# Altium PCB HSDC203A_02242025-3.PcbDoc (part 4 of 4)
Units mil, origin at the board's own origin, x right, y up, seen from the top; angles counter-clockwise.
Board outline 5612.98 x 3012.39 mil, 6 copper layers (Top Layer, GND1, Signal1, Power, GND2, Bottom Layer), stack 60.4 mil thick; 301 components, 211 nets, 1107 pads, 249 vias.
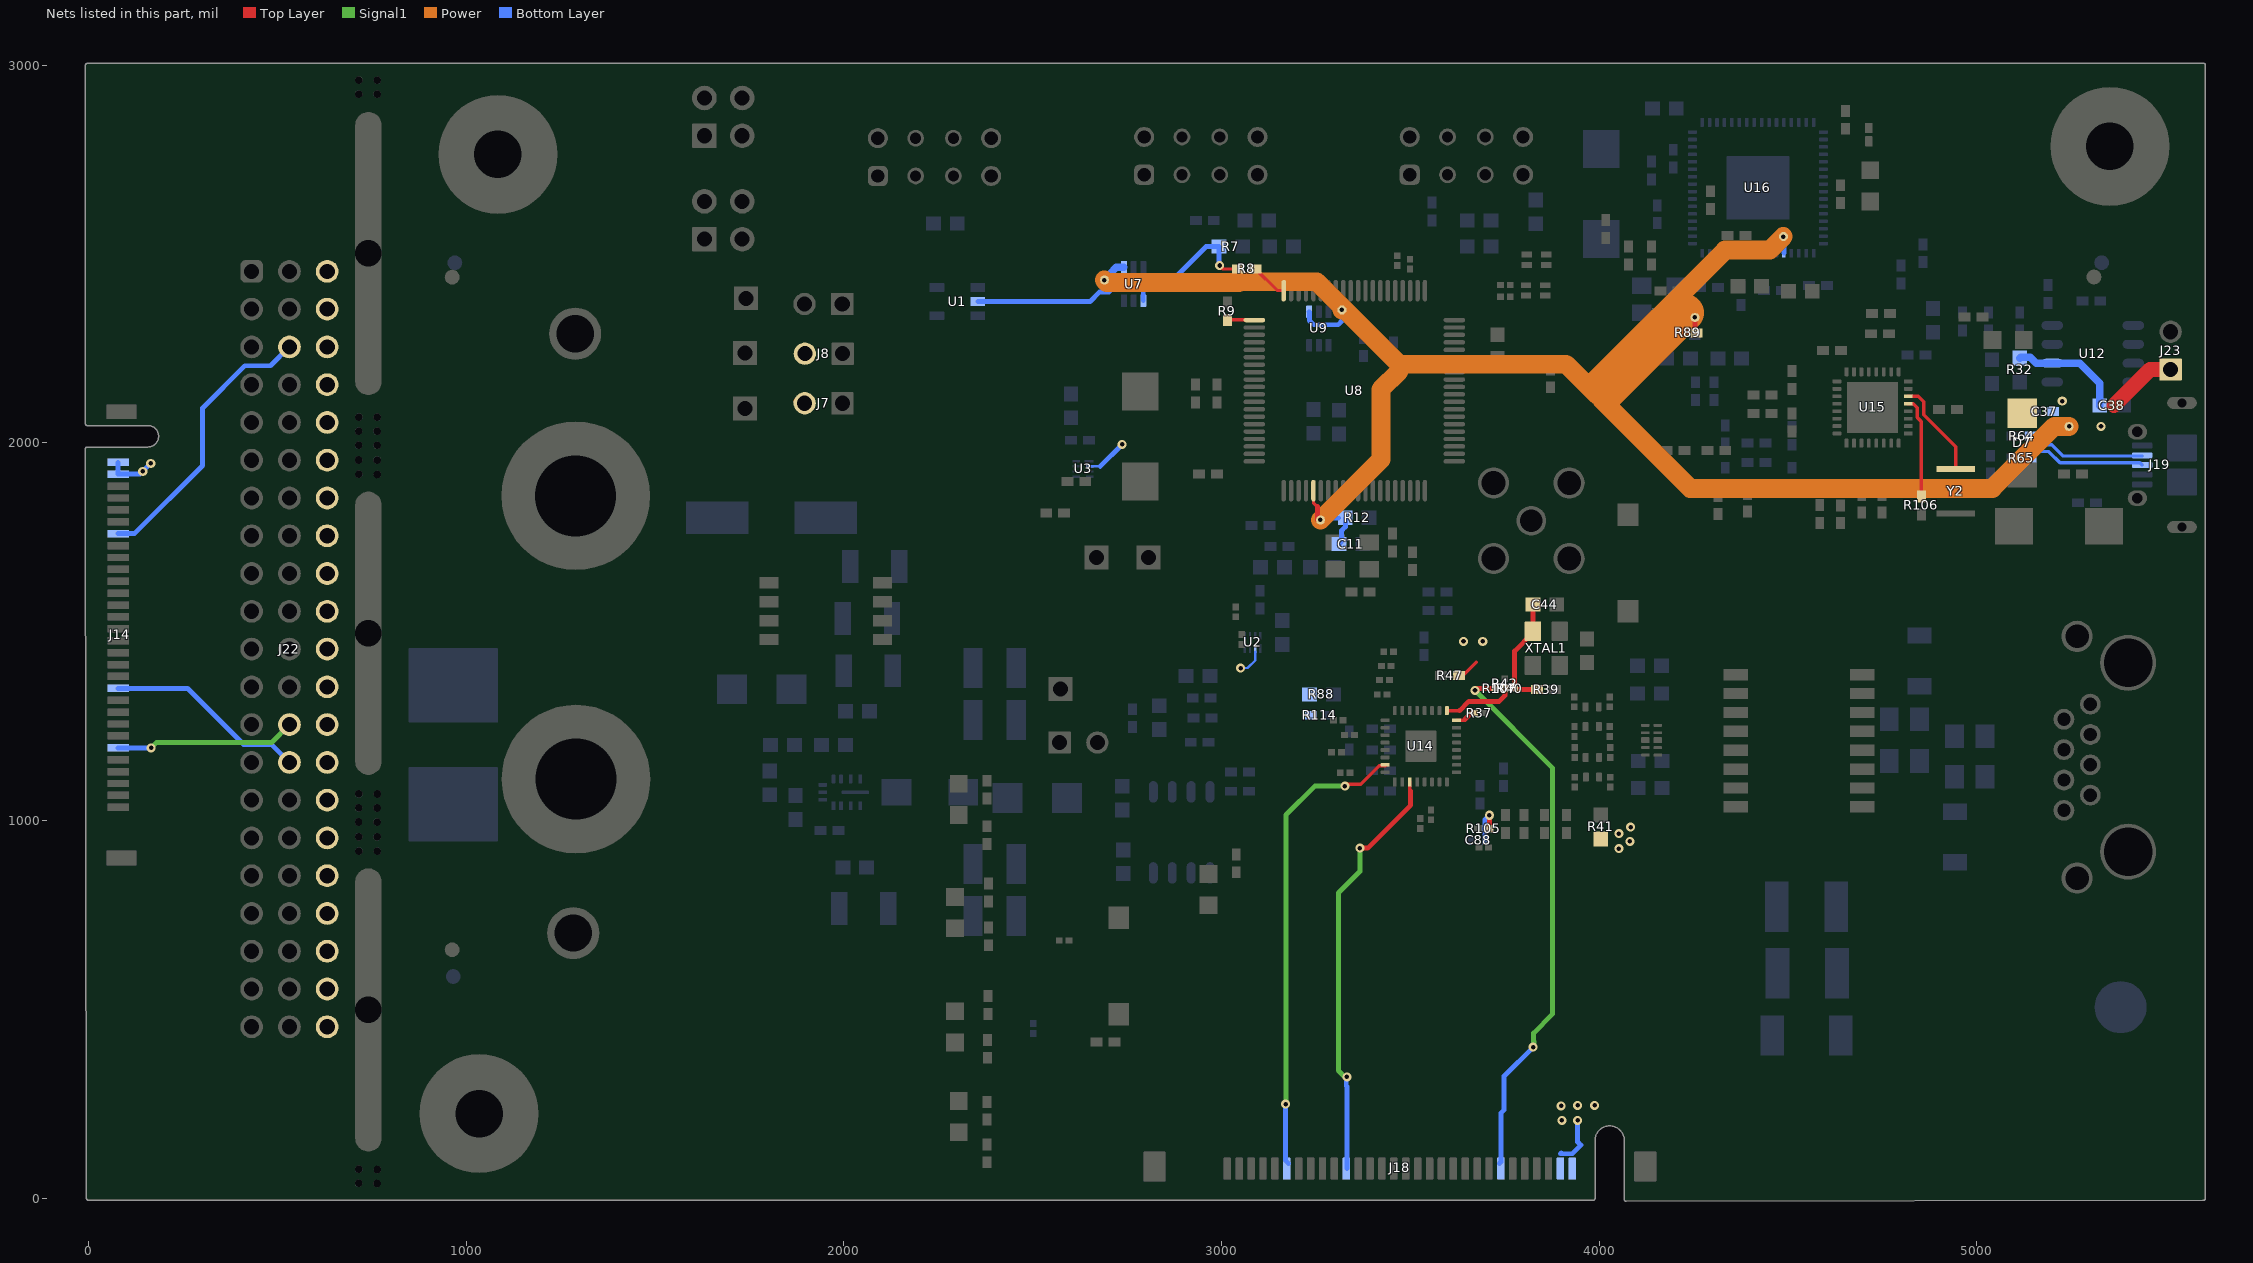
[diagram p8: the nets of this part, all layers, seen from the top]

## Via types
v1: diameter 24, hole 12, Top Layer to Bottom Layer, tented both sides, 227 vias
v2: diameter 19.68, hole 7.87, Top Layer to Bottom Layer, 17 vias
v3: diameter 19.68, hole 7.87, Top Layer to Bottom Layer, tented both sides, 5 vias

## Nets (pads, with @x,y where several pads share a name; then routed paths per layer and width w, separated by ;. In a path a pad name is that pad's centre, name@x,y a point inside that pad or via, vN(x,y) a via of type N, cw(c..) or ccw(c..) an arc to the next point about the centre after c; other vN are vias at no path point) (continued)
TX_D3: J18.40 U14.27 | length 1130.5
  Top Layer w9: 3498.34,1077.61 U14.27@3498.3,1102.52
  Top Layer w13: v1(3366.56,927.23) 3386.94,927.23 3500.71,1041.01 3500.71,1078.06 3499.75,1079.02
  Signal1 w13: v1@3330.32,317.53 3309.59,338.25 3309.59,808.85 3366.56,865.82 v1(3366.56,927.23)
  Bottom Layer w13: v1(3331.83,321.47) 3330.32,319.96 3330.32,297.53 3331.9,295.94 J18.40@3331.9,78.74
TX_D3_EXT: J14.40 J22.41 | length 534.7
  Bottom Layer w13: J14.40@78.74,1350.39 262.3,1350.39 410.69,1202 484.65,1202 J22.41@532.28,1154.36
TX_EN: J18.50 U14.23 | length 1244.5
  Top Layer w9: v1(3326.62,1091.36) 3331.25,1096 3368.18,1096 3417.59,1145.41 3433.38,1145.41 U14.23@3433.38,1147.8
  Signal1 w13: v1@3170.87,249.44 3170.87,1015.42 3246.8,1091.36 v1(3326.62,1091.36)
  Bottom Layer w13: v1(3169.82,249.44) 3169.82,99.82 J18.50@3176.97,92.66
TX_EN_EXT: J14.50 J22.38 | length 479
  Signal1 w13: v1(165.87,1192.91) 179.75,1206.79 484.71,1206.79 J22.38@532.28,1254.36
  Bottom Layer w13: J14.50@78.74,1192.91 v1(165.87,1192.91)
TX_OPT: R7.1 R8.1 U1.2 U7.4 | length 841.4
  Top Layer w9: v1(2994.85,2469.85) 3004.08,2460.63 R8.1@3043.17,2460.63
  Bottom Layer w13: U1.2@2354.59,2374.33 2651.69,2374.33 2677.39,2400.03 2702.59,2400.03 2720.45,2417.88 2782.71,2417.88 2792.91,2407.68 ; U7.4@2792.91,2376.57 2792.91,2407.68 ; 2805.6,2407.67 2846.68,2407.67 2958.92,2519.91 R7.1@2993.17,2519.91 2993.17,2471.53 v1(2994.85,2469.85) ; 2805.59,2407.68 2792.91,2407.68
UART_RX: R9.2 U8.41 | length 72.1
  Top Layer w9: R9.2@3015.35,2324.8 3016.57,2326.02 U8.41@3086.92,2326.02
UART_TX: R8.2 U8.40 | length 97.8
  Top Layer w9: R8.2@3090.42,2460.63 3147.27,2403.77 U8.40@3164.67,2403.77
USB_N: J19.2 R64.1 | length 316.8
  Bottom Layer w9: R64.1@5142.86,2018.93 5166.48,1995.31 5197.66,1995.31 5227.34,1965.63 J19.2@5437.6,1965.63
USB_P: J19.3 R65.1 | length 318.1
  Bottom Layer w9: R65.1@5141.42,1959.88 5158.85,1977.31 5190.2,1977.31 5219.89,1947.63 5431.68,1947.63 J19.3@5437.6,1941.71
USB_VBUS: C11.2 C37.1 C38.1 D7.1 J23.1 R12.2 R32.2 R89.2 U7.1 U8.65 U9.1 U12.2 U16.53 | length 5335.8
  Top Layer w9: U8.65@3243.41,1874.25 U8.65@3243.41,1873.69 3243.41,1841.98 3253.83,1831.57
  Top Layer w13: v1@3253.83,1796.15 3253.83,1831.57 ; v1(4253.53,2332.67) 4253.53,2295.5 R89.2@4257.75,2291.28
  Top Layer w40: 5363.12,2099.48 5458.05,2194.41 J23.1@5512.8,2194.41
  Power w50: v1(2689.66,2431.26) 2695.94,2424.98 3046.42,2424.98 3048.21,2426.76 3252.08,2426.76 3318.5,2360.34 v1(3318.5,2352.36) 3326.48,2352.36 3470.4,2208.44 ; v1@3262.16,1796.36 3422.01,1956.22 3422.01,2142.05 3470.4,2190.43 3470.4,2208.44 ; 3994.68,2126.21 3959.96,2160.92 ; 4007.48,2139.01 4007.48,2113.41 4240.96,1879.92 5040.94,1879.92 5204.99,2043.96 v1(5244.21,2043.96) ; v1(4487.31,2546.45) 4451.5,2510.63 4333.16,2510.63 3983.45,2160.92 3959.96,2160.92 ; 3470.4,2208.44 3912.45,2208.44 3959.96,2160.92
  Power w100: 4024.7,2142.18 4227.55,2345.03
  Bottom Layer w13: U9.1@3232.11,2347.44 3233.07,2346.48 3233.07,2324.04 3244.12,2312.99 3308.66,2312.99 3318.5,2322.83 v1(3318.5,2352.36) v1@3318.5,2356.73 ; v1@3266.81,1801.02 R12.2@3310.34,1801.02 ; C11.2@3310.9,1732.28 3317.82,1739.2 3317.82,1767.87 3327.75,1777.79 R12.2@3327.75,1802 ; v1(4487.31,2546.45) 4489.06,2544.7 U16.53@4489.06,2502.28
  Bottom Layer w20: v1(2689.66,2431.26) 2721.4,2465.16 U7.1@2741.73,2465.16 ; R32.2@5113.3,2224.89 5115.8,2227.4 5140.56,2227.4 5156.74,2211.22 U12.2@5199.41,2211.22 5272.51,2211.22 5325.16,2158.58 C38.1@5325.16,2099.18
  other v1: 3261.94,1796.15 5328.46,2043.96 5225.87,2110.72
VDDA3P3: J7.2 R41.2 | length 14.8
  Power w25: J7.2@1879.75,2109.78 J7.2@1894.53,2109.78
  other v1: 4051.85,926.25 4081.38,945.27 4051.85,965.81 4082.86,982.99
VDDIO: C88.2 J8.2 J18.2 J18.4 R47.2 R88.1 R105.2 R114.1 U2.2 U3.2 | length 488.3
  Top Layer w9: R47.2@3628.26,1384.29 3633.57,1378.97 3674.28,1419.68
  Top Layer w13: R105.2@3709.26,978.33 v1(3709.26,1014.46)
  Bottom Layer w6: U3.2@2651.18,1938.22 2679.01,1938.22 ; v1(3050.48,1403.97) 3068.93,1403.97 3089.17,1424.21 U2.2@3089.17,1447.87
  Bottom Layer w12: 3899.61,120.47 3897.24,118.11 3928.74,118.11
  Bottom Layer w13: 2679.01,1938.22 v1(2736.89,1996.1) ; C88.2@3698.04,948.8 3698.04,1003.24 v1(3709.26,1014.46) ; 3928.74,118.11 3951.48,140.85 3942.9,149.44 v1(3942.9,206.69)
  other v1: 3901.38,206.69 3899.21,245.02 3942.58,246.06 3987.8,246.06 3640.71,1474.91 3691.61,1474.91
VDDIO_EXT: J14.2 J14.4 J22.3 J22.6 J22.9 J22.12 J22.15 J22.18 J22.21 J22.24 J22.27 J22.30 J22.33 J22.36 J22.39 J22.42 J22.45 J22.48 J22.51 J22.54 J22.57 J22.60 J22.63 | length 129.8
  Bottom Layer w13: J14.2@78.74,1948.82 J14.4@78.74,1917.32 136.26,1917.32 v1(143.88,1924.94) v1(165.09,1946.16)
XI: R40.1 R42.2 R107.1 U14.9 | length 188.2
  Top Layer w9: U14.9@3596.76,1291.5 3630.48,1291.5
  Top Layer w13: 3630.48,1291.5 3655.01,1316.02 3734.89,1316.02 3750.11,1331.24 R40.1@3750.11,1349.64
XI_C: C44.1 R39.1 R40.2 XTAL1.1 | length 303.1
  Top Layer w13: C44.1@3824.48,1571.94 3824.48,1501.65 XTAL1.1@3824.41,1501.57 3824.41,1497.36 3776.1,1449.05 R40.2@3776.1,1349.64 3778.69,1347.04 R39.1@3835.74,1347.04
XI_S: J18.14 R107.2 | length 1447
  Top Layer w13: v1@3672.35,1347.04 3674.95,1349.64 R107.2@3724.13,1349.64
  Signal1 w13: v1(3671.12,1345.24) 3876.14,1140.21 3876.14,487.51 3826.36,437.72 3826.36,415.87 3827.17,415.06 v1@3827.17,401.58
  Bottom Layer w13: J18.14@3735.63,92.66 3739.76,96.8 3739.76,225.87 3748.42,234.53 3748.42,323.92 v1(3824.86,400.35)
XI_S_EXT: J14.14 J22.8 | length 747.6
  Bottom Layer w13: J14.14@78.74,1759.84 121.76,1759.84 302.41,1940.5 302.41,2092.73 414.05,2204.36 482.28,2204.36 J22.8@532.28,2254.36
XO: R37.2 U14.8 | length 55.3
  Top Layer w9: U14.8@3622.35,1265.91 3645.31,1265.91
  Top Layer w13: 3644.49,1267.91 3661.62,1285.05 R37.2@3669.69,1285.05
XTAL1: U15.30 Y2.1 | length 259.7
  Top Layer w9: U15.30@4818.22,2123.46 4844.63,2123.46 4859.31,2108.77 4859.31,2074.43 4944.01,1989.74 Y2.1@4944.01,1931.33
XTAL2: R106.2 U15.29 | length 268.1
  Top Layer w9: U15.29@4818.22,2103.77 4831.84,2103.77 4842.4,2093.21 4842.4,2080.49 4842.44,2080.46 4842.44,2067.44 4853.04,2056.84 R106.2@4853.04,1858.1
pads on no net: FID1.1 FID2.1 FID3.1 FID4.1 FID5.1 FID6.1 H5.0 H6.0 H7.0 H8.0 J14.17 J14.33 J14.53 J14.57 J14.59 J18.17 J18.33 J18.53 J18.57 J18.59 J19.4 T2.4 T2.5 T2.12 T2.13 U1.1 U4.1 U4.4 U4.5 U4.8 U5.1 U5.4 U5.5 U5.8 U6.1 U6.4 U6.5 U6.8 U8.1 U8.2 U8.3 U8.5 U8.6 U8.7 U8.8 U8.9 U8.10 U8.12 U8.13 U8.15 U8.16 U8.17 U8.27 U8.29 U8.30 U8.31 U8.32 U8.33 U8.34 U8.35 U8.36 U8.37 U8.38 U8.39 U8.42 U8.43 U8.44 U8.45 U8.48 U8.53 U8.54 U8.55 U8.56 U8.57 U8.58 U8.59 U8.60 U8.72 U8.73 U8.74 U8.75 U10.8 U13.3@4122.24,1213.15 U13.8@4155.12,1213.15 U15. U15.5 U15.9 U15.13 U15.17 U15.21 U15.32 U16.3 U16.4 U16.5 U16.6 U16.7 U16.8 U16.10 U16.12 U16.13 U16.18 U16.19 U16.22 U16.23 U16.24 U16.25 U16.26 U16.27 U16.28 U16.29 U16.30 U16.31 U16.34 U16.35 U16.36 U16.41 U16.42 U16.45 U16.46 U16.47 U16.48 U16.60 U16.61 U16.62 U16.63

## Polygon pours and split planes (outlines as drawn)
GND_EXT on Bottom Layer "BOTTOM_LAYER_GND_EXT_P156" (solid, remove dead copper, pour order 156): 0,3000 0,8.46 680.71,8.46 680.71,3000
GND on Bottom Layer "NONET_L01_P-001" (solid, pour order 10): 4070.03,844.13 4503.76,844.13 4503.76,215.91 4070.83,215.91
VDDIO on Bottom Layer "BOTTOM_LAYER_VDDIO_P011" (solid, remove dead copper, pour order 11): 3974.5,50.86 3974.5,180.4 4005.32,211.52 4004.96,265.27 3885.59,265.27 3885.59,50.86
5V on Bottom Layer "BOTTOM_LAYER_5V_P013" (solid, remove dead copper, pour order 13): 2301.43,1511.73 2301.43,663.16 2706.76,663.16 2706.76,1419.27 2614.3,1511.73
5V-12V on Bottom Layer "BOTTOM_LAYER_5V-12V_P019" (solid, remove dead copper, pour order 19): 1791.94,1910.91 2090.15,1910.92 2090.15,712.6 1791.94,712.6
NetJ4_1 on Bottom Layer "BOTTOM_LAYER_NETJ4_1_P022" (solid, remove dead copper, pour order 22): 1559.21,1318.9 1559.21,514.54 970.28,514.54 cw(c970.28,654.91) 829.91,654.91 829.91,1318.9
no net on Bottom Layer "BOTTOM_LAYER_NONET_P023" (solid, remove dead copper, pour order 23): 907.08,1545.28 1300.79,1545.28 1300.79,1654.36 1507.48,1654.36 1507.48,2369.2 ccw(c1416.05,2369.2) 1416.05,2460.63 936.38,2460.63 ccw(c936.38,2362.44) 838.19,2362.44 838.19,1614.17 ccw(c907.08,1614.17)
MCU_VCC on Bottom Layer "BOTTOM_LAYER_MCU_VCC_P027" (solid, remove dead copper, pour order 27): 4727.89,2312.99 4731,2211.73 5049.51,2207.35 5049.51,2245.67 5234.71,2245.67 5234.71,2312.99
USB_VBUS on Bottom Layer "BOTTOM_LAYER_USB_VBUS_P035" (solid, remove dead copper, pour order 35): 5094.32,2242.08 5094.32,2189.55 5183.22,2189.55 5183.22,2028.27 5355.91,2028.27 5355.91,2242.08
GND on Bottom Layer "BOTTOM_LAYER_GND_P104" (solid, remove dead copper, pour order 104): 2994.73,155.12 2994.73,50.86 3957.48,50.86 3957.48,155.12
no net on Bottom Layer "BOTTOM_LAYER_NONET_P112" (solid, remove dead copper, pour order 112): 840.84,1538.62 840.84,1257.68 1300.79,1257.68 1300.79,1538.62
NetD3_1 on Bottom Layer "BOTTOM_LAYER_NETD3_1_P116" (solid, remove dead copper, pour order 116): 2532.57,1245.7 2532.28,999.63 2659.06,999.63 2659.06,1119.22 2615.75,1119.22 2615.75,1245.7
Sys_5V on Bottom Layer "BOTTOM_LAYER_SYS_5V_P120" (solid, remove dead copper, pour order 120): 2629.37,1267.91 2629.37,1054.36 2845.77,1054.36 2845.77,994.71 2885.82,994.71 2885.82,1267.91
VDDIO on Bottom Layer "BOTTOM_LAYER_VDDIO_P132" (solid, remove dead copper, pour order 132): 3028.01,1419.47 3028.01,1259.41 3253.83,1259.41 3253.83,1419.47
3V3_OPT on Bottom Layer "BOTTOM_LAYER_3V3_OPT_P134" (solid, remove dead copper, pour order 134): 2568.42,2102.74 2639.37,2102.74 2639.37,2147.31 2954.3,2147.31 2954.37,2269.05 2568.42,2269.05
MCU_VCC on Bottom Layer "BOTTOM_LAYER_MCU_VCC_P136" (solid, remove dead copper, pour order 136): 3930.1,2712.14 3930.1,2482.27 4127.06,2482.27 4133.15,2482.27 4133.15,2488.36 4133.15,2653.55 4165.43,2653.55 4216.47,2704.59 4216.47,2752.74 4217.6,2753.86 4148.51,2753.86 4149.89,2712.14
3V3_LDO on Bottom Layer "BOTTOM_LAYER_3V3_LDO_P146" (solid, remove dead copper, pour order 146): 1944.28,2435.35 1947.18,2432.45 1947.18,1975.43 2087.83,1975.43 2237.47,1825.8 2237.47,1700.28 2237.47,1553.51 2544.59,1553.51 2736.71,1553.51 2736.71,1511.91 2773.52,1489.65 2783,1494.62 2793.62,1579.48 2652.62,1660.97 2442.52,2025.08 2442.52,2295.73 2129.32,2295.73 2139.37,2305.79 2139.37,2435.35
3V3_LDO on Bottom Layer "BOTTOM_LAYER_3V3_LDO_P147" (solid, remove dead copper, pour order 147): 2662.8,1634.67 2662.8,1560.49 2750.26,1473.03 2842.47,1473.03 2842.47,931.17 2962.23,931.17 2962.23,1634.67
GND on Bottom Layer "BOTTOM_LAYER_GND_P148" (solid, remove dead copper, pour order 148): 800.76,3020.11 800.76,-7.38 4263.12,-7.38 4263.12,1793.62 5603.19,1793.62 5603.19,3020.11
EARTH_GND on Bottom Layer "Bottom Layer-EARTH_GND" (solid, remove dead copper, pour order 151): 5045.26,361.97 5598.04,361.97 5598.04,624.69 5598.04,646.57 5598.04,1514.3 4594.92,1514.3 4594.93,358.8
GND on Power "POWER_GND_P162" (solid, remove dead copper, pour order 162): 798.82,2974.44 798.82,1.38 4262.15,1.38 4262.15,1762.16 5615.05,1762.16 5615.05,2974.44
3V3_LDO on Power "TOP_LAYER_NONET_P-001" (solid, remove dead copper, pour order 161): 2953.72,1290.07 2404.28,1839.51 2404.28,1940.03 2195.3,2149.01 1962.79,2149.01 1962.79,1933.14 2219.93,1933.14 2219.93,947.88 2953.72,947.88
VDDIO on Power "Power-VDDIO" (solid, remove dead copper, pour order 160): 3029.46,1249.66 2428.69,1850.44 2428.69,1945.95 2213.78,2160.86 2114.58,2160.86 1836.77,2160.86 cw(c1836.77,2203.14) 1794.49,2203.14 1794.49,2274.86 cw(c1839.15,2274.87) 1839.15,2319.53 2775.29,2319.53 3331.11,1515.75 4271.14,1515.75 4271.14,186.58 3754.34,186.58 3754.34,492.73 4129.26,492.73 4129.26,1003.03 3029.46,1003.03
VDDA3P3 on Power "POWER_VDDA3P3_P016" (solid, remove dead copper, pour order 16): 1776.58,694.12 3817.29,694.12 3817.29,999.16 4107.78,999.16 4107.78,515.92 1530.63,515.92 1546.85,611.96 1546.85,2148.29 1947.18,2148.29 1947.18,1985.63 1776.58,1985.63
MCU_VCC on Power "POWER_MCU_VCC_P015" (solid, remove dead copper, pour order 15): 3194.93,2319.27 3194.93,2106.24 2875.3,2106.24 2875.3,1769.56 3023.23,1769.56 3023.23,1589.94 3447.33,1589.94 3447.33,1769.56 5600,1769.56 5600,2544.52 ccw(c5368.94,2544.53) 5368.93,2775.59 4068.91,2775.59 ccw(c4068.9,2645.27) 3938.58,2645.26 3938.58,2319.27
3V3_OPT on Power "POWER_3V3_OPT_P018" (solid, remove dead copper, pour order 18): 1851.97,2438.98 1851.97,2356.52 ccw(c1881.71,2356.51) 1881.71,2326.77 2773.93,2326.77 2773.93,2117.46 2972.35,2117.46 2972.35,2438.98 2341.8,2438.97 cw(c2335.69,2474.95) 2314.57,2445.19 cw(c2347.99,2475.15) 2303.17,2477.6 2303.17,2522.36 cw(c2327.88,2515.84) 2327.75,2541.39 3873.53,2549.2 ccw(c3866.21,2579.36) 3897.24,2579.36 3897.24,2629.92 ccw(c3859.85,2629.92) 3859.84,2667.32 1994.92,2667.32 ccw(c1994.91,2524.38) 1851.97,2524.37
5V-12V on Power "POWER_5V-12V_P025" (solid, remove dead copper, pour order 25): 1791.94,1917.36 1791.94,734.44 2173.94,734.44 2173.94,1917.36
VDDIO_EXT on Power "POWER_VDDIO_EXT_P034" (solid, remove dead copper, pour order 34): 0,3000 0,8.46 680.71,8.46 680.71,3000
GND_EXT on GND1 "GND1_GND_EXT_P153" (solid, remove dead copper, pour order 153): 0,3000 0,8.46 680.71,8.46 680.71,3000
GND on GND1 "GND1_GND_P031" (solid, remove dead copper, pour order 31): 802.47,3049.2 802.47,0 4397.86,0 4397.86,1768.25 5606.4,1768.25 5606.4,3049.2
EARTH_GND on GND1 "NONET_L01_P-001" (solid, pour order 145): 4591.61,1514.3 5590.74,1514.3 5590.74,806 4590.49,806
GND on Top Layer "TOP_LAYER_GND_P164" (solid, remove dead copper, pour order 164): 800.76,3020.11 800.76,-7.38 4263.12,-7.38 4263.12,1754.89 5603.19,1754.89 5603.19,3020.11
NetC64_1 on Top Layer "TOP_LAYER_NONET_P-001" (solid, remove dead copper, pour order 163): 5045.17,1727.99 5045.17,2011.86 5380.86,2011.86 5380.86,1965.63 5249.5,1965.63 5249.5,1727.99
GND_EXT on Top Layer "TOP_LAYER_GND_EXT_P152" (solid, remove dead copper, pour order 152): 0,3000 0,8.46 680.71,8.46 680.71,3000
USB_VBUS on Top Layer "TOP_LAYER_USB_VBUS_P006" (solid, remove dead copper, pour order 6): 5077.76,2150.77 5077.76,2028.94 5382.94,2028.94 5382.94,2150.77
GND on Top Layer "TOP_LAYER_GND_P026" (solid, remove dead copper, pour order 26): 2994.73,155.12 2994.73,82.63 3957.48,82.63 3957.48,155.12
VDDA3P3 on Top Layer "TOP_LAYER_VDDA3P3_P106" (solid, remove dead copper, pour order 106): 4100,991.85 4096.42,995.44 4052.02,995.44 4042.16,985.58 3987.9,985.58 3980.91,978.55 3981.28,918.66 3987.8,912.19 4088.19,912.19 4100,924
5V on Top Layer "TOP_LAYER_5V_P108" (solid, remove dead copper, pour order 108): 2617.72,2814.96 3647.61,2814.96 3647.61,2598.43 2741.88,2598.43 2741.88,1118.95 2099.53,1118.95 2099.53,2814.96
VDDIO on Top Layer "TOP_LAYER_VDDIO_P114" (solid, remove dead copper, pour order 114): 3604.64,1493.29 3726.76,1493.29 3726.76,1455.77 3726.76,1372.47 3604.64,1372.47
5V on Top Layer "TOP_LAYER_5V_P142" (solid, remove dead copper, pour order 142): 3652.21,2755.91 3652.21,2578.74 2727.95,2578.74 2727.95,1154.54 2334.25,1154.54 2334.25,2755.91
5V on Top Layer "TOP_LAYER_5V_P144" (solid, remove dead copper, pour order 144): 2300.46,2666.73 2299.62,2665.89 2299.62,1153.99 2479.82,1153.99 2479.82,2558.46 2646.27,2558.46 2646.27,2666.73
GND on Signal1 "SIGNAL1_GND_P157" (solid, remove dead copper, pour order 157): 798.82,2982.9 798.82,9.84 4262.15,9.84 4262.15,1770.62 5615.05,1770.62 5615.05,2982.9
GND_EXT on Signal1 "SIGNAL1_GND_EXT_P154" (solid, remove dead copper, pour order 154): 0,3000 0,8.46 680.71,8.46 680.71,3000
GND_EXT on GND2 "GND2_GND_EXT_P155" (solid, remove dead copper, pour order 155): 0,3000 0,8.46 680.71,8.46 680.71,3000
GND on GND2 "GND2_GND_P033" (solid, remove dead copper, pour order 33): 798.82,3050.24 798.82,0 4262.29,0 4262.29,1771.43 5623.45,1771.43 5623.45,3050.24

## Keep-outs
Keep-Out Layer:
  text ".Layer_Name" at 677,-858.49 h60

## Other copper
Top Layer:
  pour cut-out: 4613.49,2088.58 4616.65,2085.42 4616.65,1968.5 4616.1,1968.5 4579.83,1932.23 4530.42,1981.64 4530.42,2068.14
  pour cut-out: 4933.75,1947.08 4900.06,1980.77 4900.06,2111.84 4840.16,2171.74 4733.57,2171.74 4733.57,2238.64 4766.84,2271.91 4766.84,2283.46 4868.45,2283.46 5006.24,2145.67 5014.35,2145.67 5014.35,1956.19 5005.24,1947.08
  pour cut-out: 3138.79,1851.61 3138.79,1733.11 3137.96,1732.28 3140.71,1729.53 3267.43,1729.53 3267.43,1836.25 3267.43,1851.61
  pour cut-out: 3536.61,2024.3 3687.41,2024.05 3687.41,1835.21 3658.78,1806.58 3658.78,1697.67 3731.46,1697.67 3782.54,1646.59 3782.54,1527.86 3307.76,1527.86 3307.76,1647.24 3337.29,1676.77 3536.61,1676.77
  pour cut-out: 4287.84,1028.97 4221.59,1095.22 4121.65,1095.22 4121.65,214.89 4291.71,214.89
  pour cut-out: 4195.41,1906.43 4154.73,1865.75 4154.73,1834.78 4247.38,1742.13 4281.12,1775.86 4281.12,1850.61 4315.86,1885.35 4309.51,1891.69 4309.51,1929.13 4312.23,1929.13 4348.34,1965.24 4348.34,2017.24 4347.47,2017.24 4319.99,2044.72 4322.44,2047.17 4322.44,2057.09 4334.47,2057.09 4361.81,2029.74 4362.81,2030.74 4538.72,2030.74 4538.72,2036 4567.12,2064.4 4613.49,2064.4 4613.49,2156.43
  pour cut-out: 4627.75,2160.66 4553.51,2160.66 4529.13,2185.04 4493.9,2185.04 4470.08,2161.22 4468.47,2162.83 4260.39,2162.83 4174.8,2077.24 4174.8,1935.5 4203.4,1906.91
  pour cut-out: 4312.69,2277.69 4541.43,2277.69 4616.1,2352.36 4566.89,2401.57 4274.65,2401.57 4257.81,2384.74
  pour cut-out: 4294.19,1527.19 4219.76,1527.19 4176.19,1527.19 4063.28,1457.76 3978.56,1359.34 3617.29,1359.34 3617.29,1176.15 4039.48,1186.74 4049.8,1178.38 4162.07,1087.53 4294.19,1087.53
  text ".Layer_Name" at 677,-858.49 h60
GND1:
  pour cut-out: 4658.75,806.82 4658.75,1514.43 4549.96,1514.43 4549.96,806.82
  text ".Layer_Name" at 673.88,-858.49 h60
Signal1:
  text ".Layer_Name" at 673.88,-858.49 h60
Power:
  text ".Layer_Name" at 673.88,-858.49 h60
GND2:
  text ".Layer_Name" at 673.88,-858.49 h60
Bottom Layer:
  pour cut-out: 4180.81,1908.64 3918.77,1646.6 3634.75,1646.6 3634.75,1647.32 3609.94,1672.13 3483.28,1672.13 3456.41,1645.26 3450.77,1650.9 3277.73,1650.9 3277.73,1819.09 3257.7,1839.12 3251.01,1832.43 3108.13,1832.43 3108.13,1637.08 3222.32,1522.89 4025.08,1522.89 4295.82,1793.62
  pour cut-out: 4659,1431 4664.05,1425.95 5340.66,1425.95 5340.66,935.04 4658.46,935.04
  pour cut-out: 5405.12,1877.28 5232.8,1877.28 5190.2,1919.88 5189.61,1919.29 4982.36,1919.29 4900.06,2001.59 4900.06,2111.84 4840.16,2171.74 4980.17,2171.74 5019.29,2132.62 5019.29,2064.4 5128.56,2064.4 5237.17,1955.8 5405.12,1955.8
  pour cut-out: 4364.43,2062.24 4595.23,2062.24 4640.23,2017.24 4640.23,1975.77 4623.36,1975.77 4540.4,1892.81 4292.91,1892.81 4292.91,1907.67 4226.52,1974.06 4226.52,2053.32 4191.27,2088.57 4191.27,2367.91 4324.35,2401.57 4364.43,2381.89
  pour cut-out: 4459.75,2461.33 4460.24,2461.82 4460.24,2539.37 4581.89,2539.37 4602.7,2518.56 4602.7,2333.36 4597.1,2333.36 4541.43,2277.69 4460.24,2277.69
  text ".Layer_Name" at 677,-858.49 h60
Multi-Layer:
  pour cut-out: 4194.49,216.54 4200.39,210.63 4200.39,9.26 4261.05,9.26 4262.15,8.16 4262.15,215.28

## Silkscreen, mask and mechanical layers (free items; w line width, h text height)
Top Overlay:
  rectangle: 645.23,1549.09 655.23,1559.09
  lines w10: 194.66,1278.98 194.66,1444.69 ; 194.66,1577.38 194.66,1748.67 ; 633.34,2515.29 633.34,2565 ; 636.27,349.8 636.27,399.51 ; 4045.79,1070.96 4190.08,926.68 4410.24,926.68 4441.82,895.1
  text "GND" at 1408.1,2881.4 h72.83
  text "GND" at 1812.6,2881.4 h72.83
  text "LED 0" at 4770.04,2814.96 h72.83
  text "RST" at 1409.06,2791.73 h72.83
  text "TST" at 1812.6,2791.72 h72.83
  text "EZFET" at 1379.53,2755.91 h72.83 r90
  text "EZFET" at 4769.4,2722.56 h72.83
  text "MDC RX" at 3984.14,2667.32 h80 r90
  text "MDIO TX" at 2560.63,2639.01 h80 r90
  text "MDIO RX" at 3262.37,2637.63 h80 r90
  text "LED 1" at 4766.84,2629.17 h72.83
  text "GND" at 1407.53,2608.68 h72.83
  text "GND" at 1812.02,2608.68 h72.83
  text "VDDIO_EXT" at 649.5,2573.52 h50 r90
  text "MSP" at 1379.53,2519.98 h72.83 r90
  text "TST" at 1416.32,2518.98 h72.83
  text "RST" at 1816.74,2518.17 h72.83
  text "P1.3" at 3907.36,2465.16 h50
  text "MDC" at 255.74,2438.28 h50
  text "P1.2" at 3907.97,2418.06 h50
  text "P1.1" at 3907.36,2370.08 h50
  text "SYS_5V" at 5386.79,2367.53 h50
  text "MSP" at 4046.85,2356.3 h50 r90
  text "OPT" at 2084.4,2342.61 h72.83
  text "MDIO" at 255.74,2334.96 h50
  text "P1.0" at 3907.36,2325.45 h50
  text "MCU LDO" at 5176.93,2260.21 h50
  text "XI" at 289.79,2226.13 h50
  text "VDDIO" at 2078.35,2211.22 h72.83
  text "GND" at 1645.28,2175.2 h72.83 r90
  text "USB_VBUS" at 5189.92,2172.16 h50
  text "CRS" at 266.33,2136.38 h50
  text "GND" at 1192.52,2091.61 h100
  text "VDDA" at 2078.35,2086.47 h72.83
  text "COL" at 271.72,2035.75 h50
  text "SMA XI" at 3740.87,1947.18 h50
  text "RXD3" at 258.34,1931.91 h50
  text "3.3 V" at 1930.71,1878.39 h72.83 r90
  text "RXD2" at 254.94,1829.14 h50
  text "RXD1" at 256.96,1726.7 h50
  text "MDC" at 2495.27,1680.38 h50
  text "MDIO" at 2880.71,1680.38 h50
  text "PULL UP" at 2289.94,1645.09 h50 r270
  text "RXD0" at 254.94,1629.34 h50
  text "SW1" at 2170.24,1626.67 h50
  text "SW2" at 2168.7,1565.05 h50
  text "MSP RESET" at 4204.55,1554.36 h50 r90
  text "RXCLK" at 235.67,1530.96 h50
  text "SW3" at 2169.26,1508.46 h50
  text "GND" at 214.34,1463.23 h50 r90
  text "SW4" at 2169.26,1451.55 h50
  text "RXDV" at 250.88,1434.61 h50
  text "PULL DOWN" at 1753.31,1423.91 h50 r90
  text "GND" at 2364.51,1328.74 h72.83
  text "RXER" at 248.85,1325.07 h50
  text "TXEN" at 252.91,1222.64 h50
  text "5 V" at 2395.05,1191.85 h72.83
  text "TXD3" at 260.01,1127.3 h50
  text "TXD2" at 243.91,1029.46 h50
  text "COL" at 2246.32,975.34 h72.83 r90
  text "TXD1" at 259.91,933.46 h50
  text "TXD0" at 230.74,847.81 h50
  text "5V-12V" at 1143.31,825.47 h100
  text "TXCLK" at 230.74,749.93 h50
  text "3V3 LDO" at 2926.22,682.06 h50
  text "LED0" at 2246.32,668.87 h72.83 r90
  text "CLKOUT" at 188.39,650.17 h50
  text "RST" at 242.97,557.93 h50
  text "PHY RESET" at 2851.94,485.1 h50 r90
  text "PWDN" at 196.92,444.06 h50
  text "'.PRJ_Number'" at 1399.21,347.91 h108.27
  text "CLK OUT" at 2246.32,334.65 h72.83 r90
  text "DP83826AEVM" at 1399.21,236.22 h108.27
  text "CRS" at 2246.32,131.11 h72.83 r90
  text "VDDIO_EXT" at 649.74,89.57 h50 r90
  text ".Layer_Name" at 677,-858.49 h60
Bottom Overlay:
  text ".Layer_Name" at 677,-858.49 h60
Top Paste:
  text ".Layer_Name" at 677,-858.49 h60
Bottom Paste:
  text ".Layer_Name" at 677,-858.49 h60
Top Solder:
  text ".Layer_Name" at 677,-858.49 h60
  text ".Layer_Name" at 677,-858.49 h60
Bottom Solder:
  text ".Layer_Name" at 677,-858.49 h60
Drill Guide:
  text ".Layer_Name" at 677,-858.49 h60
M1 Board Outline:
  lines w10: 4071.26,-2.36 5598.03,0 ; 4071.26,0 4071.26,158.07 ccw(c4027.56,152.84) 3983.86,158.07 3983.86,0 0,0 -2.95,1984.25 157.48,1984.25 ccw(c157.48,2017.72) 157.48,2051.18 -2.95,2051.18 -2.95,3000 5600,3000 5600,0
  text ".Layer_Name" at 677,-858.49 h60
M2 Board Dimensions:
  rectangle: 100,-275 225,-150
  rectangle: 225,-400 600,-275
  lines w7: 100,-275 1100,-275 ; 225,-400 225,-150 ; 350,-400 350,-150 ; 600,-400 600,-150 ; 850,-400 850,-150 ; 100,-400 1100,-400 1100,-150 100,-150 100,-400
  text ".Layer_Name" at 677,-858.49 h60
M3 3D STEP Top:
  text ".Layer_Name" at 677,-858.49 h60
M4 3D STEP Bottom:
  text ".Layer_Name" at 677,-858.49 h60
M5 Assembly Top:
  lines w10: -192,-930.17 6408,-930.17 ; -192,-726.83 6410,-726.83 ; -192,-523.5 -192,-1133.5 3813,-1133.5 6410,-1133.5 6410,-523.5 -191.5,-523.5 -191.5,-1133.5 1384,-1133.5 ; 2273,-1133.5 2273,-523.5 ; 3540,-726.83 3540,-523.5 ; 4380,-726.83 4380,-523.5 ; 5002,-1140 5002,-937.17
  text "COMPONENTS MARKED 'DNP' SHOULD NOT BE POPULATED." at 1253.5,-318.5 h60
  text "ASSEMBLY VARIANT:" at 1253,-434 h60
  text ".VariantName" at 2289,-434 h60
  text "PCB VIEWED FROM TOP SIDE" at -128.5,-655.67 h60
  text "BOARD #:" at 2348,-655.67 h60
  text ".PRJ_Number" at 2893.5,-655.67 h60
  text "REV:" at 3738,-655.67 h60
  text ".PCB_Rev" at 4029.5,-655.67 h60
  text "SVN REV:" at 4576,-655.67 h60
  text ".VersionControl_RevNumber" at 5082,-655.67 h60
  text "TID #:" at 2348,-859 h60
  text ".TID" at 2893.5,-859 h60
  text "PLOT NAME =" at -128.5,-1064.34 h60
  text ".plot_File_Name" at 677,-1064.34 h60
  text "GENERATED    :" at 2350,-1064.34 h60
  text ".Print_Date" at 3219.5,-1064.34 h60
  text ".Print_Time" at 3948.5,-1064.34 h60
  text "TEXAS INSTRUMENTS" at 5213,-1064.34 h60
M6 Assembly Bottom:
  lines w10: -192.5,-727.33 6409.5,-727.33 ; -190.5,-930.67 6409.5,-930.67 ; 1215.5,-1140.5 1215.5,-937.67 ; 1837.5,-727.33 1837.5,-524 ; 2677.5,-727.33 2677.5,-524 ; 3944.5,-1134 3944.5,-524 ; 4833.5,-1134 6409,-1134 6409,-524 -192.5,-524 -192.5,-1134 2404.5,-1134 6409.5,-1134 6409.5,-524
  text "COMPONENTS MARKED 'DNP' SHOULD NOT BE POPULATED." at 6202,-318 h60
  text ".VariantName" at 5158,-434 h60
  text "ASSEMBLY VARIANT:" at 6197,-434 h60
  text ".VersionControl_RevNumber" at 1135.5,-656.17 h60
  text "SVN REV:" at 1641.5,-656.17 h60
  text ".PCB_Rev" at 2188,-656.17 h60
  text "REV:" at 2479.5,-656.17 h60
  text ".PRJ_Number" at 3324,-656.17 h60
  text "BOARD #:" at 3869.5,-656.17 h60
  text "PCB VIEWED FROM BOTTOM SIDE" at 6346,-656.17 h60
  text ".TID" at 3324,-859.5 h60
  text "TID #:" at 3869.5,-859.5 h60
  text "TEXAS INSTRUMENTS" at 1004.5,-1064.84 h60
  text ".Print_Time" at 2269,-1064.84 h60
  text ".Print_Date" at 2998,-1064.84 h60
  text "GENERATED    :" at 3867.5,-1064.84 h60
  text ".plot_File_Name" at 5540.5,-1064.84 h60
  text "PLOT NAME =" at 6346,-1064.84 h60
M9 Title Sheet:
  drawing of 57 lines, arcs and shapes, not listed
  text "1" at 839.84,8036.5 h70
  text "2" at 3335.5,8036.5 h70
  text "3" at 5824.84,8036.5 h70
  text "4" at 8331.51,8036.5 h70
  text "5" at 10830.5,8036.5 h70
  text "6" at 13335.5,8036.5 h70
  text "A" at -316.5,6893.5 h70
  text "A" at 14483.5,6893.5 h70
  text "B" at -316.5,4513.5 h70
  text "B" at 14483.5,4513.5 h70
  text "C" at -316.5,2138.5 h70
  text "C" at 14483.5,2138.5 h70
  text "PROJECT TITLE:" at 11443.5,277.5 h45
  text ".PRJ_Title" at 11493.5,144.17 h70
  text "DESIGNED FOR:" at 11443.5,-23.5 h45
  text ".PRJ_Customer" at 11493.5,-163.5 h70
  text "D" at -316.5,-231.5 h70
  text "D" at 14483.5,-231.5 h70
  text "FILE NAME:" at 11443.5,-323.5 h45
  text ".PCB_File_Name_No_Path" at 11493.5,-443.5 h70
  text "Texas Instruments (TI) and/or its licensors do not warrant the accuracy or completeness of this specification" at 6474,-605.34 h45
  text "ENGINEER:" at 11443.5,-613.5 h45
  text "LAYOUT BY:" at 12948.5,-613.5 h45
  text "or any information contained therein. TI and/or its licensors do not warrant that this design will meet" at 6429.01,-718 h45
  text ".PRJ_Engineer" at 11493.5,-768.49 h70
  text ".PCB_Layout" at 12999,-768.49 h70
  text "the specifications, will be suitable for your application or fit for any particular purpose, or will operate in" at 6429.01,-830.67 h45
  text ".Layer_Name" at 677,-858.49 h60
  text "ALTIUM DESIGNER VERSION:" at 12948.5,-923.5 h45
  text "an implementation. TI and/or its licensors do not warrant that the design is production worthy. You should" at 6429.01,-943.33 h45
  text "completely validate and test your design implementation to confirm the system functionality for your application." at 6474,-1056 h45
  text ".print_Scale" at 11493.5,-1056.83 h70
  text ".Application_BuildNumber" at 12999,-1056.83 h70
  text "1" at 839.84,-1263.5 h70
  text "2" at 3335.5,-1263.5 h70
  text "3" at 5824.84,-1263.5 h70
  text "4" at 8331.51,-1263.5 h70
  text "5" at 10830.5,-1263.5 h70
  text "6" at 13335.5,-1263.5 h70
M10 Fab Notes:
  drawing of 189 lines, arcs and shapes, not listed
  text "DESIGN INFORMATION" at 12482.02,6356.17 h60
  text "MIN. TRACK WIDTH:" at 11837.46,6224.05 h60
  text "6" at 12933.7,6224.05 h60
  text "MIL" at 13088.46,6224.05 h60
  text "MIN. CLEARANCE:" at 11837.46,6099.92 h60
  text "7" at 12933.7,6099.92 h60
  text "MIL" at 13088.46,6099.92 h60
  text "MIN. VIA PAD SIZE:" at 11837.46,5975.8 h60
  text "24" at 12903.71,5975.8 h60
  text "MIL" at 13088.46,5975.8 h60
  text "0.05mm (2MIL)" at 12532.46,5845.9 h60
  text "MINIMUM ANNULAR RING" at 11508.23,5837.67 h60
  text "EXTERNAL" at 13240.46,5837.67 h60
  text "PER" at 11708.23,5727.55 h60
  text "IPC-D-275 CLASS 2 LEVEL C" at 11928.23,5727.54 h60
  text "MIL, HOLES" at 13416.46,5627.07 h60
  text "+/-" at 13024,5618.48 h60
  text "+/-" at 13878,5618.48 h60
  text "REGISTRATION TOLERANCES:" at 11508.23,5617.42 h60
  text "METAL" at 12708,5617.42 h60
  text "5" at 13284.2,5617.42 h60
  text "3" at 14117.2,5617.42 h60
  text "MIL" at 14233.46,5617.42 h60
  text "HOLE SIZE TOLERANCE (UNLESS OTHERWISE SPECIFIED):" at 11508.23,5519.1 h60
  text "+/-" at 13878,5516.23 h60
  text "3" at 14117.2,5515.17 h60
  text "MIL" at 14233.46,5515.17 h60
  text "MATERIAL:" at 11433.46,5377.52 h60
  text "FR-4 High Tg" at 12419.9,5249 h60
  text "X" at 12275.46,5241.01 h60
  text "FR-408" at 11854.46,5236.49 h60
  text "OTHER" at 13342.46,5236.49 h60
  text "62 MIL (1.6mm) +/-10%" at 12174.56,5093.46 h60
  text "X" at 12054.46,5091.01 h60
  text "THICKNESS:" at 11508.23,5085.24 h60
  text "OTHER" at 13459.46,5085.24 h60
  text "TOLERANCE:" at 11508.23,4946.92 h60
  text "X" at 12356.46,4946.92 h60
  text "ANSI IPC-6012 TYPE 3 CLASS 2" at 12534.48,4946.92 h60
  text "OTHER +/-" at 12534.46,4802.73 h60
  text "BOW & TWIST:" at 11508.23,4657.54 h60
  text "X" at 12356.46,4657.54 h60
  text "ANSI IPC-6012 TYPE 3 CLASS 2" at 12534.48,4657.54 h60
  text "OTHER +/-" at 12534.46,4510.85 h60
  text "DRILLING:" at 11433.46,4380.23 h60
  text "NC_DRILL FILES" at 13194.46,4275.04 h60
  text "REFERENCE:" at 11508.23,4271.1 h60
  text "X" at 12165.46,4271.01 h60
  text "AS SHOWN" at 12343.46,4271.1 h60
  text "X" at 13066.46,4271.1 h60
  text "OTHER" at 13492.46,4128.85 h60
  text "PTH COPPER THICKNESS:" at 11507.91,4125.32 h60
  text "X" at 12647.14,4125.32 h60
  text "20-30 um" at 12775.14,4125.32 h60
  text "BOARD FINISH:" at 11433.46,3977.73 h60
  text "SILKSCREEN:" at 11588.68,3867.6 h60
  text "X" at 12546.46,3867.6 h60
  text "TOP" at 12663.46,3867.6 h60
  text "X" at 13056.46,3867.6 h60
  text "BOTTOM" at 13174.46,3867.6 h60
  text "SILKSCREEN COLOR:" at 11588.68,3712.41 h60
  text "X" at 12545.46,3712.41 h60
  text "WHITE" at 12663.46,3712.41 h60
  text "OTHER" at 13174.46,3712.41 h60
  text "X" at 12676.46,3568.96 h60
  text "GREEN" at 12794.46,3568.96 h60
  text "OTHER" at 13412.46,3568.96 h60
  text "SOLDER RESIST COLOR:" at 11588.68,3562.1 h60
  text "X" at 12676.46,3414.71 h60
  text "MATTE" at 12794.46,3414.71 h60
  text "SEMI-GLOSS" at 13412,3414.07 h60
  text "IMMERSION GOLD (ENIG)" at 12494.46,3241.94 h60
  text "ENEPIG" at 13832,3234.72 h60
  text "SURFACE FINISH:" at 11433.46,3233.72 h60
  text "X" at 12316.46,3233.72 h60
  text "IMM. TIN/SILVER OR EQUIV" at 11763,3096.4 h60
  text "OTHER" at 13194.46,3092.47 h60
  text "ARRAY/PANEL:" at 11433.46,2937.09 h60
  text "CUT AND TRIM PER M1 BOARD OUTLINE" at 12494.46,2928.87 h60
  text "N.C. ROUTE" at 12494.46,2792.9 h60
  text "X" at 13182.46,2792.9 h60
  text "V. SCORE" at 13360.46,2792.9 h60
  text "CERTIFICATION:" at 11433.46,2663.77 h60
  text "MATERIALS AND WORKMANSHIP FOR ALL PCBS" at 12158.46,2663.77 h60
  text "TO MEET OR EXCEED THE REQUIREMENTS OF:" at 12158.46,2569.71 h60
  text "X" at 11795.97,2441.08 h60
  text "ANSI IPC-A-600F CLASS ->" at 11923.96,2441.08 h60
  text "X" at 13571.97,2441.08 h60
  text "2" at 13681.96,2441.08 h60
  text "1" at 13366.96,2439.58 h60
  text "3" at 14035.96,2439.58 h60
  text "X" at 12607.97,2293.39 h60
  text "RoHS" at 12735.96,2293.39 h60
  text "OTHER" at 13380.36,2293.39 h60
  text "PER ORDER" at 13777.42,2293.39 h60
  text "ALL BOARDS MUST MEET OR EXCEED UL94-V0 REQUIREMENTS." at 11461,2139.57 h60
  text "PCB MUST BEAR THE UL94V-0 UL REGISTERED MATERIAL ID NUMBER" at 11461,2023.5 h60
  text "ADDITIONAL REQUIREMENTS:" at 11433.46,1854.08 h60
  text "MICROSECTION:" at 11508.23,1746.95 h60
  text "YES" at 12413.96,1746.95 h60
  text "REQUIRED" at 13275.46,1602.62 h60
  text "BARE BOARD ELEC. TEST:" at 11508.23,1599.76 h60
  text "NONE" at 12813.96,1599.76 h60
  text "X" at 13157.46,1599.76 h60
  text "PER ORDER" at 13867.46,1599.76 h60
  text "XX MIL VIAS REQUIRE NON-CONDUCTIVE FILL AND PLANARIZE" at 11676.38,1394.82 h59
  text "XX MIL VIAS REQUIRE CONDUCTIVE FILL AND PLANARIZE" at 11684.38,1290.84 h60
  text "OUTER XX MIL TRACES REQUIRE 50 OHM SINGLE-ENDED IMPEDANCE" at 11683.39,1127.46 h58
  text "LAYER 2 & 3 (INNER LAYERS) XX MIL WIDE, XX MIL SPACE / TRACES REQUIRE 100 OHM DIFFERENTIAL IMPEDANCE" at 11675.39,891.74 h60
  text "IMPEDANCE CONTROL / Differential Impedance should be 100ohm (+/-10%) /       All 9mil wide differential traces on Top and Bottom Layer. /       Differential traces should have 9mil line spacing. / Single Ended Impedance should be 50ohm (+/-10%) /      All 13mil wide traces on Top and Bottom Layer." at 6349.29,202.83 h75
  text ".Layer_Name" at 677,-858.49 h60
M11 Gerber Information:
  lines w10: -192,-930.17 6408,-930.17 ; -192,-726.83 6410,-726.83 ; -192,-523.5 -192,-1133.5 3813,-1133.5 6410,-1133.5 6410,-523.5 -191.5,-523.5 -191.5,-1133.5 1384,-1133.5 ; 2273,-1133.5 2273,-523.5 ; 3540,-726.83 3540,-523.5 ; 4380,-726.83 4380,-523.5 ; 5002,-1140 5002,-937.17
  text "ALL ARTWORK VIEWED FROM TOP SIDE" at -128.5,-655.67 h60
  text "BOARD #:" at 2348,-655.67 h60
  text ".PRJ_Number" at 2893.5,-655.67 h60
  text "REV:" at 3738,-655.67 h60
  text ".PCB_Rev" at 4029.5,-655.67 h60
  text "SVN REV:" at 4576,-655.67 h60
  text ".VersionControl_RevNumber" at 5082,-655.67 h60
  text "LAYER NAME =" at -128.5,-858.49 h60
  text "TID #:" at 2348,-859 h60
  text ".TID" at 2893.5,-859 h60
  text "PLOT NAME =" at -128.5,-1064.34 h60
  text ".plot_File_Name" at 677,-1064.34 h60
  text "GENERATED    :" at 2350,-1064.34 h60
  text ".Print_Date" at 3219.5,-1064.34 h60
  text ".Print_Time" at 3948.5,-1064.34 h60
  text "TEXAS INSTRUMENTS" at 5213,-1064.34 h60
M12 Stackup:
  drawing of 399 lines, arcs and shapes, not listed
  text "Layer" at 4069.46,6115.12 h60
  text "Name" at 4479.38,6115.12 h60
  text "Material" at 5409.12,6115.12 h60
  text "Thickness" at 6268.89,6115.12 h60
  text "Constant" at 6918.72,6115.12 h60
  text "Board Layer Stack" at 7488.58,6115.12 h60
  text "Top Overlay" at 4479.38,5995.12 h60
  text "Top Solder" at 4479.38,5875.12 h60
  text "Solder Resist" at 5409.12,5875.12 h60
  text "0.70mil" at 6268.89,5875.12 h60
  text "3.5" at 6918.72,5875.12 h60
  text "1" at 4069.46,5755.12 h60
  text "Top Layer" at 4479.38,5755.12 h60
  text "1.40mil" at 6268.89,5755.12 h60
  text "Dielectric 1" at 4479.38,5635.12 h60
  text "FR-4 High TG" at 5409.12,5635.12 h60
  text "7.00mil" at 6268.89,5635.12 h60
  text "4.2" at 6918.72,5635.12 h60
  text "2" at 4069.46,5515.12 h60
  text "GND1" at 4479.38,5515.12 h60
  text "1.40mil" at 6268.89,5515.12 h60
  text "Dielectric1" at 4479.38,5395.12 h60
  text "FR-4 High TG" at 5409.12,5395.12 h60
  text "14.00mil" at 6268.89,5395.12 h60
  text "4.2" at 6918.72,5395.12 h60
  text "3" at 4069.46,5275.12 h60
  text "Signal1" at 4479.38,5275.12 h60
  text "1.40mil" at 6268.89,5275.12 h60
  text "Dielectric 2" at 4479.38,5155.12 h60
  text "FR-4 High TG" at 5409.12,5155.12 h60
  text "10.00mil" at 6268.89,5155.12 h60
  text "4.2" at 6918.72,5155.12 h60
  text "4" at 4069.46,5035.12 h60
  text "Power" at 4479.38,5035.12 h60
  text "1.40mil" at 6268.89,5035.12 h60
  text "Dielectric 4" at 4479.38,4915.12 h60
  text "FR-4 High TG" at 5409.12,4915.12 h60
  text "14.00mil" at 6268.89,4915.12 h60
  text "4.2" at 6918.72,4915.12 h60
  text "5" at 4069.46,4795.12 h60
  text "GND2" at 4479.38,4795.12 h60
  text "1.40mil" at 6268.89,4795.12 h60
  text "Dielectric 3" at 4479.38,4675.12 h60
  text "FR-4 High TG" at 5409.12,4675.12 h60
  text "7.00mil" at 6268.89,4675.12 h60
  text "4.2" at 6918.72,4675.12 h60
  text "6" at 4069.46,4555.12 h60
  text "Bottom Layer" at 4479.38,4555.12 h60
  text "1.40mil" at 6268.89,4555.12 h60
  text "Bottom Solder" at 4479.38,4435.12 h60
  text "Solder Resist" at 5409.12,4435.12 h60
  text "0.40mil" at 6268.89,4435.12 h60
  text "3.5" at 6918.72,4435.12 h60
  text "Bottom Overlay" at 4479.38,4315.12 h60
  text ".Layer_Name" at 677,-858.49 h60
M13 Component Bodies Top:
  text ".Layer_Name" at 677,-858.49 h60
M14 Component Bodies Bottom:
  text ".Layer_Name" at 677,-858.49 h60
M15 Courtyards Top:
  text ".Layer_Name" at 677,-858.49 h60
M16 Courtyards Bottom:
  text ".Layer_Name" at 677,-858.49 h60
Drill Drawing:
  drawing of 156 lines, arcs and shapes, not listed
  text "Symbol" at 6611.93,3942.85 h72
  text "Quantity" at 6912.49,3942.85 h72
  text "Finished Hole Size" at 7244.49,3942.85 h72
  text "Plated" at 7881.06,3942.85 h72
  text "Hole Type" at 8140.2,3942.85 h72
  text "Drill Layer Pair" at 8515.35,3942.85 h72
  text "Hole Tolerance" at 9239.68,3942.85 h72
  text "28" at 6912.49,3818.53 h60
  text "20.00mil (0.508mm)" at 7244.49,3818.53 h60
  text "NPTH" at 7881.06,3818.53 h60
  text "Round" at 8140.2,3818.53 h60
  text "Top Layer - Bottom Layer" at 8515.35,3818.53 h60
  text "C" at 6586.64,3808.54 h55.25
  text "22" at 6912.49,3694.21 h60
  text "7.87mil (0.200mm)" at 7244.49,3694.21 h60
  text "PTH" at 7881.06,3694.21 h60
  text "Round" at 8140.2,3694.21 h60
  text "Top Layer - Bottom Layer" at 8515.35,3694.21 h60
  text "227" at 6912.49,3569.89 h60
  text "12.00mil (0.305mm)" at 7244.49,3569.89 h60
  text "PTH" at 7881.06,3569.89 h60
  text "Round" at 8140.2,3569.89 h60
  text "Top Layer - Bottom Layer" at 8515.35,3569.89 h60
  text "B" at 6586.64,3559.9 h55.25
  text "12" at 6912.49,3445.57 h60
  text "29.53mil (0.750mm)" at 7244.49,3445.57 h60
  text "PTH" at 7881.06,3445.57 h60
  text "Round" at 8140.2,3445.57 h60
  text "Top Layer - Bottom Layer" at 8515.35,3445.57 h60
  text "8" at 6912.49,3321.25 h60
  text "35.04mil (0.890mm)" at 7244.49,3321.25 h60
  text "PTH" at 7881.06,3321.25 h60
  text "Round" at 8140.2,3321.25 h60
  text "Top Layer - Bottom Layer" at 8515.35,3321.25 h60
  text "G" at 6586.64,3311.26 h55.25
  text "12" at 6912.49,3196.93 h60
  text "35.43mil (0.900mm)" at 7244.49,3196.93 h60
  text "PTH" at 7881.06,3196.93 h60
  text "Round" at 8140.2,3196.93 h60
  text "Top Layer - Bottom Layer" at 8515.35,3196.93 h60
  text "6" at 6912.49,3072.61 h60
  text "39.37mil (1.000mm)" at 7244.49,3072.61 h60
  text "PTH" at 7881.06,3072.61 h60
  text "Round" at 8140.2,3072.61 h60
  text "Top Layer - Bottom Layer" at 8515.35,3072.61 h60
  text "18" at 6912.49,2948.29 h60
  text "40.00mil (1.016mm)" at 7244.49,2948.29 h60
  text "PTH" at 7881.06,2948.29 h60
  text "Round" at 8140.2,2948.29 h60
  text "Top Layer - Bottom Layer" at 8515.35,2948.29 h60
  text "63" at 6912.49,2823.97 h60
  text "40.16mil (1.020mm)" at 7244.49,2823.97 h60
  text "PTH" at 7881.06,2823.97 h60
  text "Round" at 8140.2,2823.97 h60
  text "Top Layer - Bottom Layer" at 8515.35,2823.97 h60
  text "1" at 6912.49,2699.65 h60
  text "59.06mil (1.500mm)" at 7244.49,2699.65 h60
  text "PTH" at 7881.06,2699.65 h60
  text "Round" at 8140.2,2699.65 h60
  text "Top Layer - Bottom Layer" at 8515.35,2699.65 h60
  text "2" at 6912.49,2575.33 h60
  text "61.81mil (1.570mm)" at 7244.49,2575.33 h60
  text "PTH" at 7881.06,2575.33 h60
  text "Round" at 8140.2,2575.33 h60
  text "Top Layer - Bottom Layer" at 8515.35,2575.33 h60
  text "E" at 6586.64,2565.34 h55.25
  text "4" at 6912.49,2451.01 h60
  text "62.99mil (1.600mm)" at 7244.49,2451.01 h60
  text "PTH" at 7881.06,2451.01 h60
  text "Round" at 8140.2,2451.01 h60
  text "Top Layer - Bottom Layer" at 8515.35,2451.01 h60
  text "2" at 6912.49,2326.69 h60
  text "98.43mil (2.500mm)" at 7244.49,2326.69 h60
  text "PTH" at 7881.06,2326.69 h60
  text "Round" at 8140.2,2326.69 h60
  text "Top Layer - Bottom Layer" at 8515.35,2326.69 h60
  text "3" at 6912.49,2202.37 h60
  text "125.98mil (3.200mm)" at 7244.49,2202.37 h60
  text "PTH" at 7881.06,2202.37 h60
  text "Round" at 8140.2,2202.37 h60
  text "Top Layer - Bottom Layer" at 8515.35,2202.37 h60
  text "2" at 6912.49,2078.05 h60
  text "128.00mil (3.251mm)" at 7244.49,2078.05 h60
  text "PTH" at 7881.06,2078.05 h60
  text "Round" at 8140.2,2078.05 h60
  text "Top Layer - Bottom Layer" at 8515.35,2078.05 h60
  text "F" at 6586.64,2068.06 h55.25
  text "2" at 6912.49,1953.73 h60
  text "214.57mil (5.450mm)" at 7244.49,1953.73 h60
  text "PTH" at 7881.06,1953.73 h60
  text "Round" at 8140.2,1953.73 h60
  text "Top Layer - Bottom Layer" at 8515.35,1953.73 h60
  text "A" at 6586.64,1943.74 h55.25
  text "3" at 6912.49,1829.41 h60
  text "70.00mil (1.778mm)" at 7244.49,1829.41 h60
  text "NPTH" at 7881.06,1829.41 h60
  text "Slot" at 8140.2,1829.41 h60
  text "Top Layer - Bottom Layer" at 8515.35,1829.41 h60
  text "D" at 6586.64,1819.42 h55.25
  text "2" at 6912.49,1705.09 h60
  text "23.62mil (0.600mm)" at 7244.49,1705.09 h60
  text "PTH" at 7881.06,1705.09 h60
  text "Slot" at 8140.2,1705.09 h60
  text "Top Layer - Bottom Layer" at 8515.35,1705.09 h60
  text "2" at 6912.49,1580.77 h60
  text "27.56mil (0.700mm)" at 7244.49,1580.77 h60
  text "PTH" at 7881.06,1580.77 h60
  text "Slot" at 8140.2,1580.77 h60
  text "Top Layer - Bottom Layer" at 8515.35,1580.77 h60
  text "419 Total" at 6912.49,1456.45 h60
  text "Slot definitions :" at 6611.93,1369.42 h60
  text "Routed Path Length" at 7062.64,1369.42 h60
  text "= Calculated from tool start centre position to tool end centre position." at 7602.38,1369.42 h60
  text "Hole Length" at 7062.64,1319.69 h60
  text "= Routed Path Length + Tool Size = Slot length as defined in the PCB layout" at 7402.58,1319.69 h60
  text ".Layer_Name" at 677,-858.49 h60
M17 Embedded Cavity:
  text ".Layer_Name" at 677,-858.49 h60
M18 Embedded Assembly:
  text ".Layer_Name" at 677,-858.49 h60
M19 Embedded Keepout:
  text ".Layer_Name" at 677,-858.49 h60

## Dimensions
-2.95,3000 to 5600,3000 on M2 Board Dimensions
0,0 to 3983.86,-2.36 on M2 Board Dimensions
0,0 to -2.95,3000 on M2 Board Dimensions
100,-400 to 1100,-400 on M2 Board Dimensions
